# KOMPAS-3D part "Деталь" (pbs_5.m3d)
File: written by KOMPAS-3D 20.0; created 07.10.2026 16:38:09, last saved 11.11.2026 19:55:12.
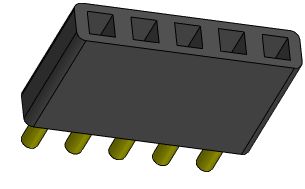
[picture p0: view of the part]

Document properties: Полное имя файла: D:\myProjects\Progect_esp32\box_compas\разъемы\pbs_5.m3d

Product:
- Part/product: Деталь
    Масса: 0.0015581

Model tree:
1. Эскиз:1
2. Элемент выдавливания:1
     Расстояние 1 = 8.5
3. Эскиз:2  (with: Элемент выдавливания:1)
4. Элемент выдавливания:2
     Расстояние 1 = 3
5. Массив по сетке:2  (with: Элемент выдавливания:2, Эскиз:2)  (5 pattern instances)
     Шаг 1 = 2.54; Угол раствора = 90
6. Эскиз:3  (with: Элемент выдавливания:1)
7. Элемент выдавливания:3
     Расстояние 2 = 8
8. Массив по сетке:3  (with: Элемент выдавливания:3, Эскиз:3)  (5 pattern instances)
     Шаг 1 = 2.54; Угол раствора = 90; Геометрический массив = 128
9. Скругление:1  (with: Элемент выдавливания:1)
     Радиус = 0.5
